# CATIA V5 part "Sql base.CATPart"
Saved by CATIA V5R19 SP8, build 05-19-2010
Part number: Sql base
Publications: "L verin", "Garde au sol", "Deport bielle fusee", "Hauteur bati", "Deport bielle bati", "Deport bielle verin", "Longueur bielle", "Origine", "A bielle", "B bielle", "D bielle", "C bielle", "D verin", "B verin", "B fusee", "C fusee", "Inf fusee", "Centre roue", "Ext roue", "A bati", "D bati", "Plan xy", "Plan yz", "Plan zx", "Axe inter diam", "Axe exter diam", "Demi epaisseur bielle", "Demi hauteur bielle", "Demi epaisseur tete bielle", "Demi epaisseur tete verin", "Deport de roue"
Bounding box of the stored display mesh (mm): x 0 to 500, y 0 to 165, z -310 to 0
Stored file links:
  C:\Users\ThinkMotion\Desktop\EU_thinkMotion\iao\IAO_MMS_Groupe3\rdalborgo\rdalborgo\Sql base.CATPart
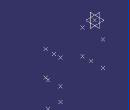
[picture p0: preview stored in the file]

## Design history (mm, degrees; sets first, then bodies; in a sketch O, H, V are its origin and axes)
Parameters
  `Longueur bielle` = 300 mm
  `Deport bielle verin` = 70 mm
  `Deport bielle bati` = 165 mm
  `Hauteur bati` = 200 mm
  `Deport bielle fusee` = 120 mm
  `Garde au sol` = 110 mm
  `L verin` = 250.0382 mm {= ((`Longueur bielle`**2 + `Hauteur bati`**2 )**0.5)/1.442}
  `Deport de roue` = 100 mm
  `Rayon roue` = 200 mm
  `Axe inter diam` = 30 mm
  `Axe exter diam` = 50 mm
  `Demi hauteur bielle` = 15 mm
  `Demi epaisseur bielle` = 20 mm
  `Demi epaisseur tete bielle` = 30 mm
  `Demi epaisseur tete verin` = 15 mm
Set1
  Point1 "Origine": (0, 0, 0)
  Point2 "A bielle": (100, 0, 0)
  Point3 "B bielle": (300 {= `Longueur bielle`}, 0, 0), relative to Point2
  Point4 "D bielle": (0, 0, -200 {= -`Hauteur bati`}), relative to Point2
  Point5 "C bielle": (300 {= `Longueur bielle`}, 0, 0), relative to Point4
  Point6 "D verin": (0, 70 {= `Deport bielle verin`}, 0), relative to Point4
  Point7 "B verin": (0, 70 {= `Deport bielle verin`}, 0), relative to Point3
  Point8 "B fusee": (0, 120 {= `Deport bielle fusee`}, 0), relative to Point3
  Point9 "C fusee": (0, 120 {= `Deport bielle fusee`}, 0), relative to Point5
  Point10 "Inf fusee": (0, 0, -110 {= -`Garde au sol`}), relative to Point9
  Point11 "Centre roue": (100 {= `Deport de roue`}, 0, 0), relative to Point10
  Point12 "Ext roue": (0, 0, 200 {= `Rayon roue`}), relative to Point11
  Point13 "A bati": (0, 165 {= `Deport bielle bati`}, 0), relative to Point2
  Point14 "D bati": (0, 165 {= `Deport bielle bati`}, 0), relative to Point4
Body1 (main body)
